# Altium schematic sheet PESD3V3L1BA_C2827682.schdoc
size 127 x 101 mm
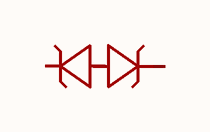
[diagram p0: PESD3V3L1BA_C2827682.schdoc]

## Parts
D?  pesd3v3l1ba_c2827682  [SOD-323_L1.7-W1.3-LS2.5-BI]  (value not drawn)

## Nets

Not connected (* = marked no-connect by the designer): D? 1(K) 2(A)

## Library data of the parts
D? = pesd3v3l1ba_c2827682: 极性:双向;反向截止电压(Vrwm):3.3V;最大钳位电压:12V;峰值脉冲电流(Ipp):35A;峰值脉冲功率(Ppp):400W;击穿电压:6V;; Manufacturer: TECH PUBLIC(台舟); AddInBom: yes; ModelId: 3c4d3117213c44d8be2b8463c3660d20; ModelTransform: 98.425,51.181,0,0,0,0,-0.001,0.006,0; polarity: 双向; Reverse Stand-Off Voltage (Vrwm): 3.3V; Maximum Clamping Voltage: 12V; Peak Pulse Current (Ipp): 35A; Peak Pulse Power Dissipation (Ppp): 400W; Breakdown Voltage: 6V; Reverse Leakage Current (Ir): 200nA; Number of Lines: 单路; level of protection: IEC 61000-4-2; Type: ESD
